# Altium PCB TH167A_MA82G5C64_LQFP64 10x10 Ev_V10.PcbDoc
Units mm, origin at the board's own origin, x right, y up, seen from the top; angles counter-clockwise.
Board outline 72.4 x 66 mm, 2 copper layers (Top Layer, Bottom Layer); 56 components, 82 nets, 364 pads, 164 vias.
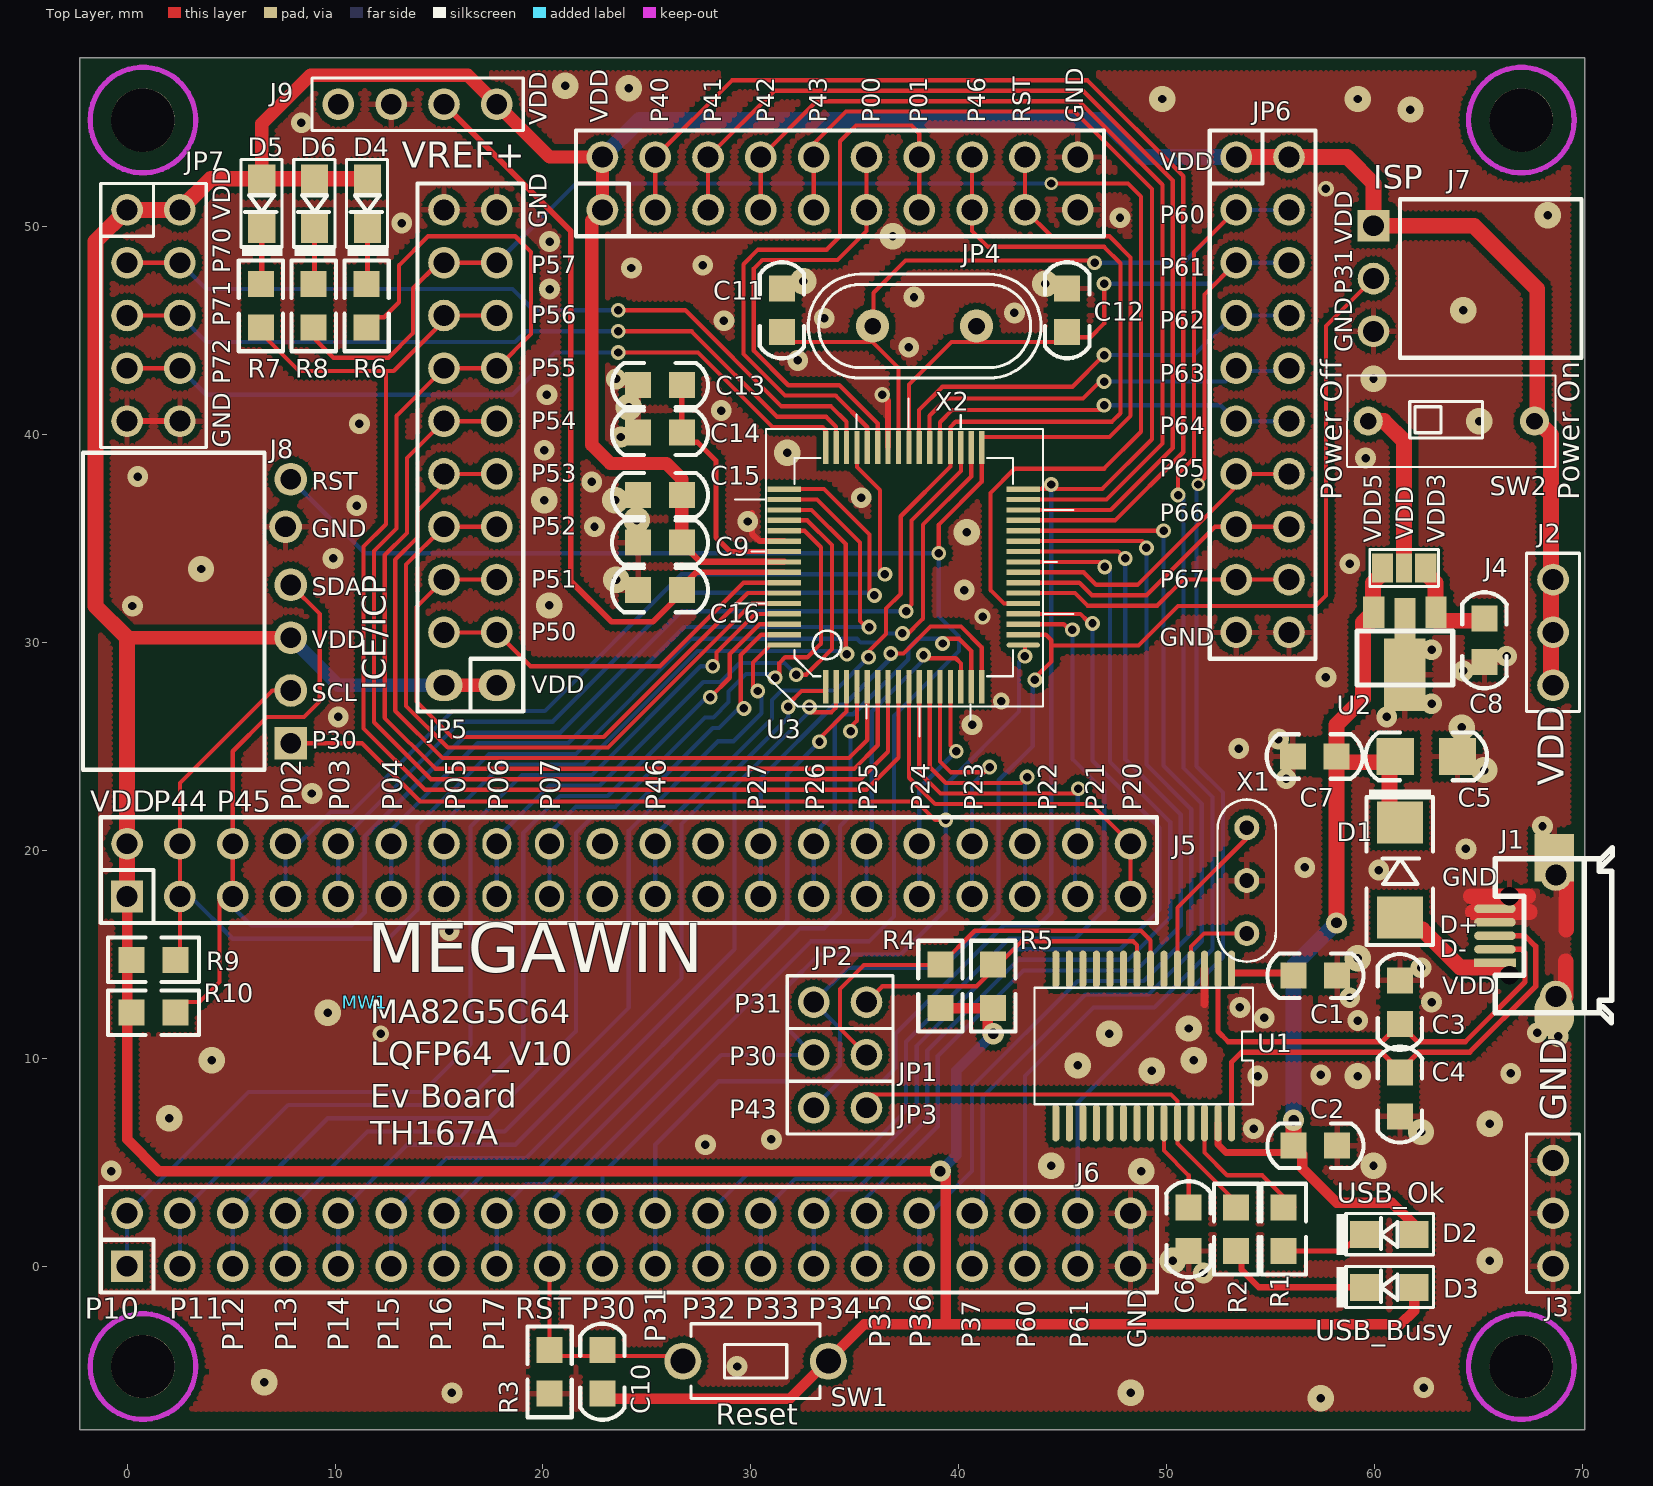
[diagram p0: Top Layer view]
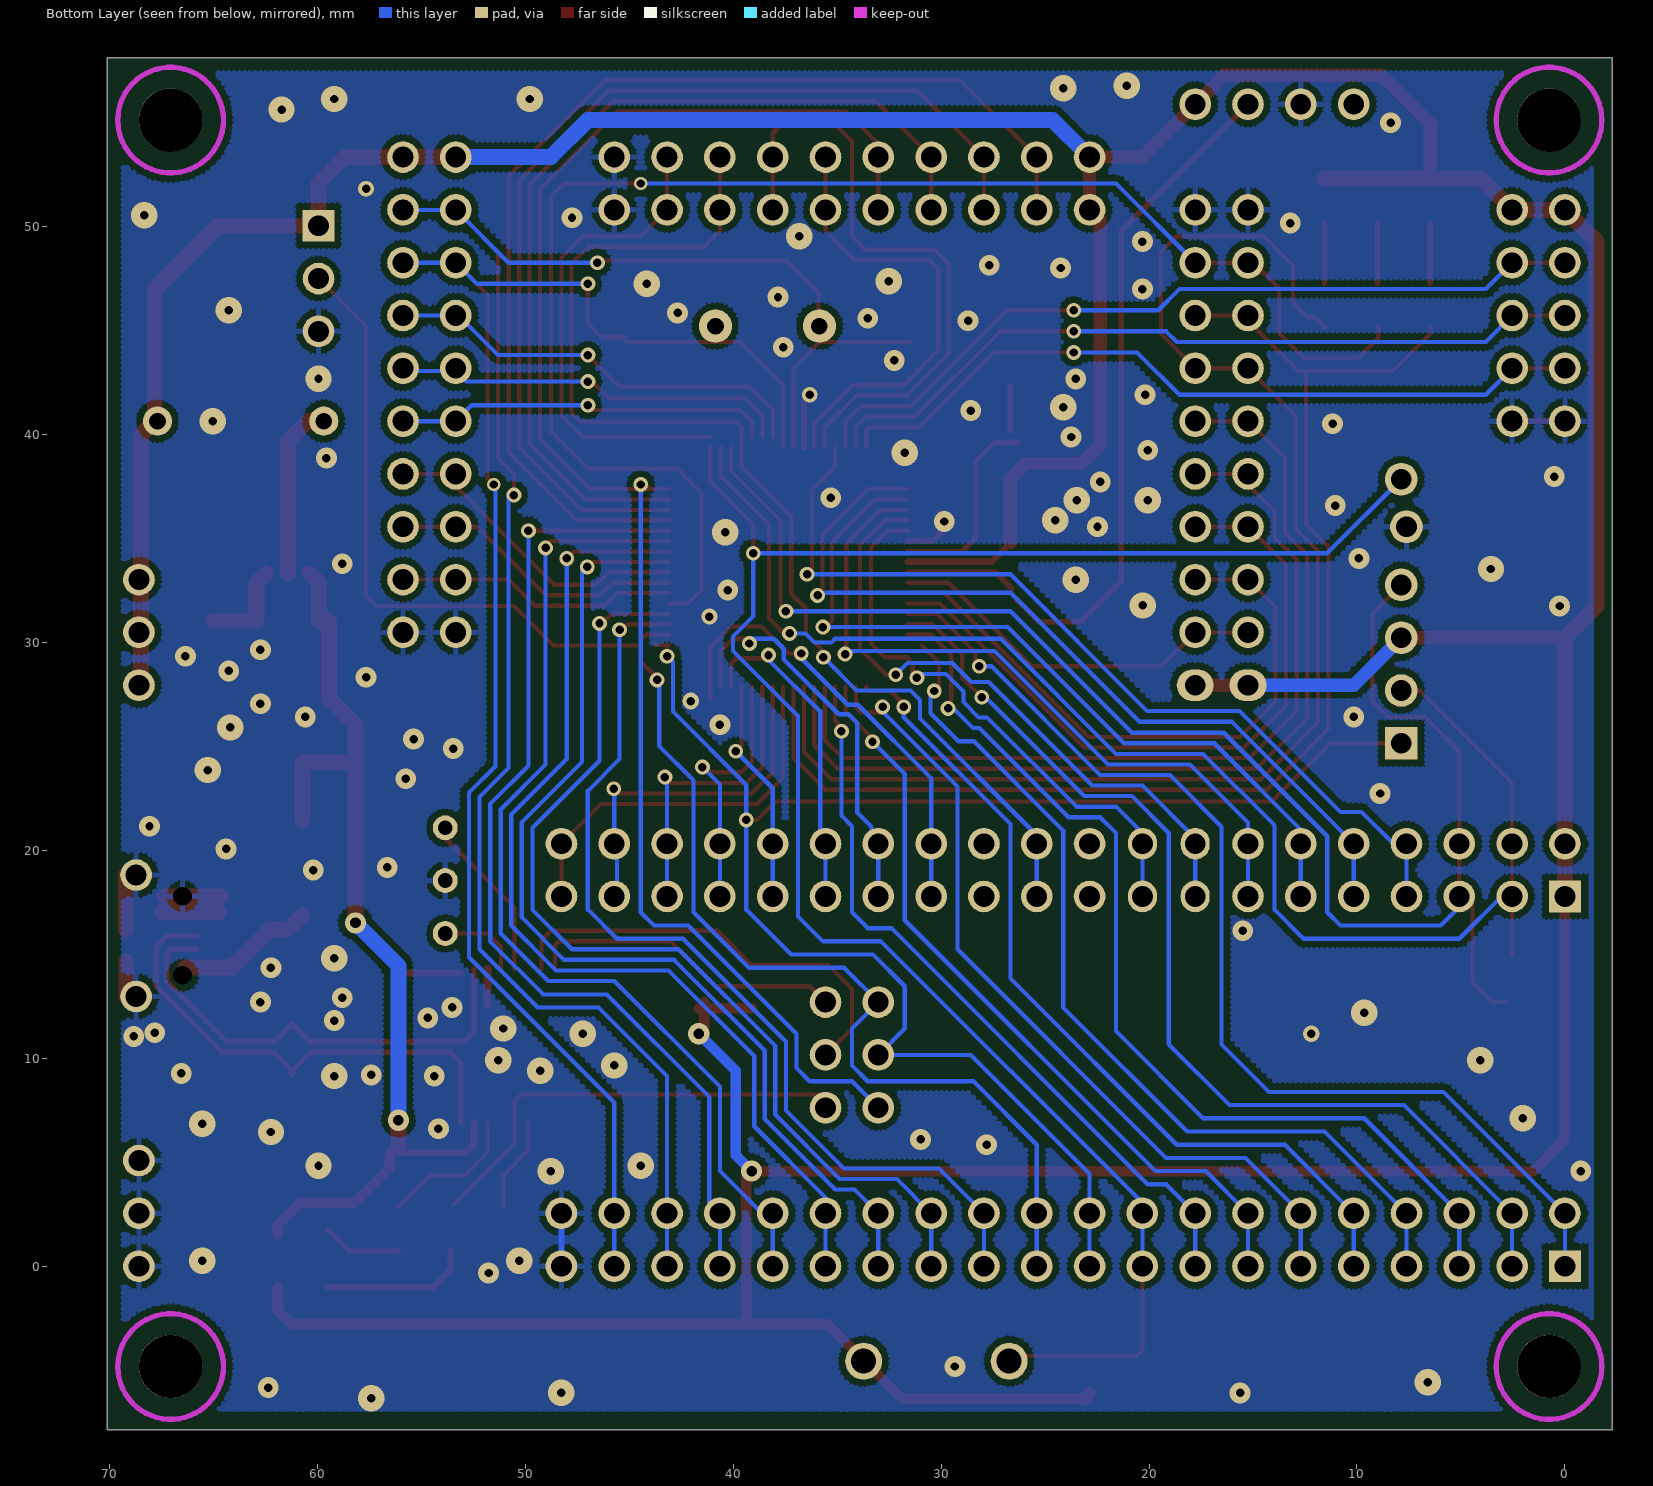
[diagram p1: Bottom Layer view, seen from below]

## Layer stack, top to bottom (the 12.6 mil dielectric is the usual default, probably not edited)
Top Layer: signal copper 0.0356
Dielectric: dielectric 0.32, FR-4, Dk 4.8
Bottom Layer: signal copper 0.0356

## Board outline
-2.286,-7.874 70.114,-7.874 70.114,58.126 -2.286,58.126

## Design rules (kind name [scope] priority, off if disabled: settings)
Clearance 12 [All] p1 off: gap=0.305
Clearance 10 [All] p2 off: gap=0.254
Clearance 6 [All] p3: gap=0.152
ComponentClearance [All] p1 off: gap=0.254 collisioncheckmode=3 verticalgap=0.254 showdistances=FALSE
HoleSize [All] p1: absolutevalues=TRUE maxlimit=12.7 minlimit=0.025 maxpercent=80.000 minpercent=20.000
MinimumSolderMaskSliver [All] p1 off: minsoldermaskwidth=0.254
PolygonConnect VIA [ISVIA] p1: connectstyle=Direct reliefconductorwidth=0.254 reliefentries=4 polygonreliefangle="90 Angle"
PolygonConnect [All] p2: connectstyle=Relief reliefconductorwidth=0.254 reliefentries=4 polygonreliefangle="90 Angle"
RoomDefinition "TH167A_MA82G5C64_LQFP64 10x10 Ev_V10" [InComponentClass('TH167A_MA82G5C64_LQFP64 10x10 Ev_V10')] p1: confinementstyle=ConfineIn formatcopy=TRUE lockcomponents=FALSE outline -14.732,-20.32 80.137,-20.32 80.137,67.056 -14.732,67.056
RoutingVias [All] p1: holewidth=0.406 width=0.635 viastyle="Through Hole" minholewidth=0.406 minwidth=0.61 maxholewidth=0.711 maxwidth=1.27
SilkToSilkClearance [All] p1 off: silktosilkclearance=0.254
SilkscreenOverComponentPads [All] p1 off: minsilkscreentomaskgap=0.254
SolderMaskExpansion [All] p1 off: expansion=0.102
Width [All] p1: maxlimit=5.08 minlimit=0.152 preferedwidth=0.254
23 further rules are at their usual default settings.

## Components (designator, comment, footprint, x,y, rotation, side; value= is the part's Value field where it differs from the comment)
C1 "4.7uF" 0805C 57.15,13.97 r0 top
C2 "0.1uF" 0805C 57.15,5.791 r180 top
C3 "15pF" 0805C 61.214,12.7 r90 top
C4 "15pF" 0805C 61.214,8.255 r270 top
C5 "4.7uF" 1206C 62.484,24.511 r0 top
C6 "0.1uF" 0805C 51.054,1.778 r90 top
C7 "0.1uF" 0805C 57.116,24.511 r180 top
C8 "4.7uF" 0805C 65.278,30.099 r270 top
C9 "0.1uF" 0805C 25.629,34.798 r0 top
C10 "1u" 0805C 22.86,-5.08 r90 top
C11 "NC" 0805C 31.496,45.974 r90 top
C12 "NC" 0805C 45.212,45.974 r90 top
C13 "4.7uF" 0805C 25.629,42.371 r180 top
C14 "0.1uF" 0805C 25.629,40.085 r0 top
C15 "4.7uF" 0805C 25.629,37.084 r180 top
C16 "0.1uF" 0805C 25.629,32.512 r180 top
D1 "1N5817" D5817_SMD_1 61.214,19.05 r270 top
D2 "Yellow" 0805D 60.706,1.524 r180 top
D3 "Red" 0805D 60.706,-1.016 r180 top
D4 "Green" 0805D 11.557,51.103 r270 top
D5 "Red" 0805D 6.477,51.103 r270 top
D6 "Green" 0805D 9.017,51.103 r270 top
J1 "Micro USB母座" JACK_USB_SMD290X220P065 65.786,15.89 r180 top
J2 "*" PS3P254 68.58,27.94 r90 top
J3 "*" PS3P254 68.58,5.08 r270 top
J4 "*" JUMP3_SMD 61.417,33.579 r0 top
J5 "CON40A" PS20X2P254#1 0,17.78 r0 top
J6 "CON40A" PS20X2P254#2 0,0 r0 top
J7 "*" PS3P254f_90 59.944,50.038 r270 top
J8 "*" PS6P254F_90 7.874,25.146 r90 top locked
J9 "CON4" PS4P254 17.78,55.88 r180 top
JP1 "JUMPER2" PS2P254 33.02,10.16 r0 top
JP2 "JUMPER2" PS2P254 33.02,12.7 r0 top
JP3 "JUMPER2" PS2P254 33.02,7.62 r0 top
JP4 "*" PS10X2P254#1 22.86,50.8 r0 top
JP5 "*" PS10X2P254#2 17.78,27.94 r90 top
JP6 "*" PS10X2P254#1 53.34,53.34 r270 top
JP7 "CON5X2" PS5X2P254 0,50.8 r270 top
MW1 "MW-A4" MEGAWIN_T 11.43,12.7 r0 top
R1 "1K" 0805R 55.626,1.778 r270 top
R2 "1K" 0805R 53.34,1.778 r270 top
R3 "47K" 0805R 20.32,-5.08 r90 top
R4 "4.7K" 0805R 39.116,13.462 r90 top
R5 "4.7K" 0805R 41.656,13.462 r90 top
R6 "1K" 0805R 11.516,46.184 r90 top
R7 "1K" 0805R 6.436,46.184 r90 top
R8 "1K" 0805R 8.976,46.184 r90 top
R9 "4.7K" 0805R 1.27,14.732 r180 top
R10 "4.7K" 0805R 1.27,12.192 r180 top
SW1 "SW TACT-SPST" SW_T_2P 30.226,-4.572 r180 top
SW2 "-" DIP2_SW 59.69,40.64 r0 top
U1 "MA101_TSSOP28" SSOP28_220P065 48.891,10.588 r180 top
U2 "AIC1734-33(SOT-89)" SOT89 61.454,31.445 r180 top
U3 "MG82FG5C64" QFP64_10X10P050 33.6,27.87 r90 top locked (schematic designator U1)
X1 "6MHz" X3P 53.848,16.002 r90 top
X2 "NC" X49U 38.354,45.212 r180 top

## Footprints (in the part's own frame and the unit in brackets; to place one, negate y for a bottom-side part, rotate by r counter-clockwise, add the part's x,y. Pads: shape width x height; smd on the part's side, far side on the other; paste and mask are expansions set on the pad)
0805C [mm]
  rect 1.25x1.25 smd: 1(-1.05,0) 2(1.05,0)
  silkscreen extent -2.31,-1.07 2.31,1.07
0805D [mm]
  rect 1.4x1.3 smd: 1(-1.192,0) 2(1.192,0)
  silkscreen extent -2.12,-1 2.53,0.98
0805R [mm]
  rect 1.25x1.25 smd: 1(-1.05,0) 2(1.05,0)
  silkscreen extent -2.18,-1.07 2.18,1.07
1206C [mm]
  rect 1.8x1.8 smd: 1(-1.5,0) 2(1.5,0)
  silkscreen extent -2.92,-1.15 2.92,1.16
D5817_SMD_1 [mil]
  rect 80x86.61 smd: 1(90,0) 2(-90,0)
  silkscreen extent -153,-63 142,63
DIP2_SW [mm]
  round 1.4 hole 0.8: 1(0,0) 2(8,0)
  silkscreen extent -1.02,-2.2 9.02,2.2
JACK_USB_SMD290X220P065 [mm]
  rect 1.9x1.8 on Mech2: 0(-2.85,-1.15) 0(-2.85,1.15)
  round 0.8 hole 0.9 unplated: 1(-0.7,1.9) 5(-0.7,-1.9)
  rect 2x0.4 smd: 1(0,1.3)
  oval 2x0.4 smd: 2(0,0.65) 3(0,0) 4(0,-0.65) 5(0,-1.3)
  round 1.524 hole 1: 5(-2.931,2.921) 5(-2.931,-2.921)
  oval 1.9x2.3 smd: 5(-2.85,3.75)
  rect 1.9x2.3 smd: 5(-2.85,-3.75)
  silkscreen extent -5.65,-4.25 -0.01,4.2
JUMP3_SMD [mil]
  rect 40x55 smd: 1(-41,0) 3(41,0)
  rect 30x55 smd: 2(0,0)
  silkscreen extent -65,-35 65,35
MEGAWIN_T [mm]
PS2P254 [mil]
  round 60 hole 39.37: 1(0,0) 2(100,0)
  silkscreen extent -50,-50 150,50
PS3P254 [mil]
  round 60 hole 39.37: 1(0,0) 2(100,0) 3(200,0)
  silkscreen extent -50,-50 250,50
PS3P254f_90 [mil]
  rect 60x60 hole 39.37: 1(0,0)
  round 60 hole 39.37: 2(100,0) 3(200,0)
  silkscreen extent -50,50 250,394
PS4P254 [mil]
  round 60 hole 39.37: 1(0,0) 2(100,0) 3(200,0) 4(300,0)
  silkscreen extent -50,-50 350,50
PS5X2P254 [mil]
  round 60 hole 39.37: 1(0,0) 2(0,100) 3(100,0) 4(100,100) 5(200,0) 6(200,100) 7(300,0) 8(300,100) 9(400,0) 10(400,100)
  silkscreen extent -50,-50 450,150
PS6P254F_90 [mil]
  rect 62x62 hole 39.37: 1(0,0)
  round 62 hole 39.37: 2(100,0) 3(200,0) 4(300,0) 5(410,10) 6(500,0)
  silkscreen extent -50,50 550,394
PS10X2P254#1 [mil]
  round 60 hole 39.37: 1(0,0) 2(0,100) 3(100,0) 4(100,100) 5(200,0) 6(200,100) 7(300,0) 8(300,100) 9(400,0) 10(400,100) 11(500,0) 12(500,100) 13(600,0) 14(600,100) 15(700,0) 16(700,100) 17(800,0) 18(800,100) 19(900,0) 20(900,100)
  silkscreen extent -50,-50 950,150
PS10X2P254#2 [mil]
  oval 60x70 hole 39.37: 1(0,0) 2(0,100)
  round 60 hole 39.37: 3(100,0) 4(100,100) 5(200,0) 6(200,100) 7(300,0) 8(300,100) 9(400,0) 10(400,100) 11(500,0) 12(500,100) 13(600,0) 14(600,100) 15(700,0) 16(700,100) 17(800,0) 18(800,100) 19(900,0) 20(900,100)
  silkscreen extent -50,-50 950,150
PS20X2P254#1 [mil]
  rect 60x60 hole 39.37: 1(0,0)
  round 60 hole 39.37: 2(0,100) 3(100,0) 4(100,100) 5(200,0) 6(200,100) 7(300,0) 8(300,100) 9(400,0) 10(400,100) 11(500,0) 12(500,100) 13(600,0) 14(600,100) 19(900,0) 20(900,100) 21(1000,0) 22(1000,100) 23(1100,0) 24(1100,100) 25(1200,0) 26(1200,100) 27(1300,0) 28(1300,100) 29(1400,0) 30(1400,100) 31(1500,0) 32(1500,100) 33(1600,0) 34(1600,100) 35(1700,0) 36(1700,100) 37(1800,0) 38(1800,100) 39(1900,0) 40(1900,100)
  oval 55x60 hole 39.37: 15(700,0) 16(700,100) 17(800,0) 18(800,100)
  silkscreen extent -50,-50 1950,150
PS20X2P254#2 [mil]
  rect 60x60 hole 39.37: 1(0,0)
  round 60 hole 39.37: 2(0,100) 3(100,0) 4(100,100) 5(200,0) 6(200,100) 7(300,0) 8(300,100) 9(400,0) 10(400,100) 11(500,0) 12(500,100) 13(600,0) 14(600,100) 15(700,0) 16(700,100) 17(800,0) 18(800,100) 19(900,0) 20(900,100) 21(1000,0) 22(1000,100) 23(1100,0) 24(1100,100) 25(1200,0) 26(1200,100) 27(1300,0) 28(1300,100) 29(1400,0) 30(1400,100) 31(1500,0) 32(1500,100) 33(1600,0) 34(1600,100) 35(1700,0) 36(1700,100) 37(1800,0) 38(1800,100) 39(1900,0) 40(1900,100)
  silkscreen extent -50,-50 1950,150
QFP64_10X10P050 [mm]
  rect 1.6x0.254 smd: 1(0,0) 2(0,-0.5) 3(0,-1) 4(0,-1.5) 5(0,-2) 6(0,-2.5) 7(0,-3) 8(0,-3.5) 9(0,-4) 10(0,-4.5) 11(0,-5) 12(0,-5.5) 13(0,-6) 14(0,-6.5) 15(0,-7) 16(0,-7.5) 33(11.5,-7.5) 34(11.5,-7) 35(11.5,-6.5) 36(11.5,-6) 37(11.5,-5.5) 38(11.5,-5) 39(11.5,-4.5) 40(11.5,-4) 41(11.5,-3.5) 42(11.5,-3) 43(11.5,-2.5) 44(11.5,-2) 45(11.5,-1.5) 46(11.5,-1) 47(11.5,-0.5) 48(11.5,0)
  oval 0.254x1.6 smd: 17(2,-9.5)
  rect 0.254x1.6 smd: 18(2.5,-9.5) 19(3,-9.5) 20(3.5,-9.5) 21(4,-9.5) 22(4.5,-9.5) 23(5,-9.5) 24(5.5,-9.5) 25(6,-9.5) 26(6.5,-9.5) 27(7,-9.5) 28(7.5,-9.5) 29(8,-9.5) 30(8.5,-9.5) 31(9,-9.5) 32(9.5,-9.5) 49(9.5,2) 50(9,2) 51(8.5,2) 52(8,2) 53(7.5,2) 54(7,2) 55(6.5,2) 56(6,2) 57(5.5,2) 58(5,2) 59(4.5,2) 60(4,2) 61(3.5,2) 62(3,2) 63(2.5,2) 64(2,2)
  silkscreen extent -2.4,-11.92 13.86,4.36
SOT89 [mm]
  rect 1.016x1.5 smd: 1(-1.5,0) 3(1.5,0)
  rect 2x3.5 smd: 2(0,3)
  rect 1.016x2.6 smd: 2(0,0.6)
  silkscreen extent -2.3,0.9 2.3,3.5
SSOP28_220P065 [mm]
  oval 0.343x1.778 smd: 1(-4.225,-3.7) 2(-3.575,-3.7) 3(-2.925,-3.7) 4(-2.275,-3.7) 5(-1.625,-3.7) 6(-0.975,-3.7) 7(-0.325,-3.7) 8(0.325,-3.7) 9(0.975,-3.7) 10(1.625,-3.7) 11(2.275,-3.7) 12(2.925,-3.7) 13(3.575,-3.7) 14(4.225,-3.7) 15(4.225,3.7) 16(3.575,3.7) 17(2.925,3.7) 18(2.275,3.7) 19(1.625,3.7) 20(0.975,3.7) 21(0.325,3.7) 22(-0.325,3.7) 23(-0.975,3.7) 24(-1.625,3.7) 25(-2.275,3.7) 26(-2.925,3.7) 27(-3.575,3.7) 28(-4.225,3.7)
  silkscreen extent -5.25,-2.8 5.25,2.8
SW_T_2P [mm]
  round 1.778 hole 1.2: 1(-3.5,0) 2(3.5,0)
  silkscreen extent -3.1,-1.8 3.1,1.8
X3P [mm]
  round 1.2 hole 0.711: 1(0,0) 2(5.08,0) 3(2.54,0)
  silkscreen extent -1.36,-1.4 6.44,1.4
X49U [mm]
  round 1.6 hole 0.8: 1(-2.5,0) 2(2.5,0)
  silkscreen extent -5.6,-2.5 5.6,2.5

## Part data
C1 C5 C8 C13 C15: library part CAP
C2 C3 C4 C6 C7 C9 C14 C16: library part "CAP NP"
C10: library part C
C11 C12: library part "C NP"
D1: library part DIODE_ZD, "Schottky Diode"
D2 D3 D4 D5 D6: library part LED
J1: library part CON5, "Connector"
J2 J3 J4 J7: library part CON3
J8: library part CON6
JP4 JP5 JP6: library part CON10X2
R1 R2 R4 R5 R6 R7 R8: library part R_Dup1
R3 R9 R10: library part R
SW2: library part SW-2
U2: library part AIC1734-33(SOT-89)_0
U3: library part MG82FG5C64_LQFP64
X1: library part CRYSTAL_RC
X2: library part CRYSTAL

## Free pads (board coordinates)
  round 3.048 hole 3.048 unplated: 0(0.762,-4.826) 0(0.762,55.118) 0(67.056,-4.826) 0(67.056,55.118)

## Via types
v1: diameter 1, hole 0.406, Top Layer to Bottom Layer, tented both sides, 66 vias
v2: diameter 0.711, hole 0.406, Top Layer to Bottom Layer, tented both sides, 44 vias
v3: diameter 1.27, hole 0.406, Top Layer to Bottom Layer, tented both sides, 43 vias
v4: diameter 1.016, hole 0.508, Top Layer to Bottom Layer, tented both sides, 4 vias
v5: diameter 0.762, hole 0.406, Top Layer to Bottom Layer, tented both sides, 3 vias
v6: diameter 0.8, hole 0.406, Top Layer to Bottom Layer, tented both sides, 2 vias
v7: diameter 0.635, hole 0.406, Top Layer to Bottom Layer, tented both sides, 2 vias

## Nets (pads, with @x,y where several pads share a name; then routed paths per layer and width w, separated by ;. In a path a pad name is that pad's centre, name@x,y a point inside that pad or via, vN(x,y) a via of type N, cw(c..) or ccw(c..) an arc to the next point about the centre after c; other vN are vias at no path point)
D+: C4.1 J1.3 U1.28 | length 24.2
  Top Layer w0.254: U1.28 53.116,9.809 53.594,10.287 60.325,10.287 61.151,9.461 C4.1@61.151,9.305 ; C4.1@61.214,9.178 61.277,9.242 61.277,9.461 62.103,10.287 64.57,10.287 67.742,13.459 67.742,15.38 67.232,15.89 J1.3
D-: C3.1 J1.2 U1.2 | length 22.8
  Top Layer w0.254: U1.2 52.466,11.288 52.959,10.795 60.359,10.795 C3.1 62.069,10.795 64.36,10.795 67.234,13.669 67.234,15.073 67.067,15.24 J1.2
GND_POWER: C1.2 C2.1 C3.2 C4.2 C5.2 C6.1 C7.2 C8.2 C9.1 C11.2 C12.2 C13.2 C14.1 C15.2 C16.2 J1.4 J1.5 J3.1 J3.2 J3.3 J6.39 J6.40 J7.3 J8.5 J9.3 JP4.19 JP4.20 JP5.19 JP5.20 JP6.19 JP6.20 JP7.9 JP7.10 R3.1 U1.3 U2.2 U3.42 U3.54 X1.3 | length 21.6
  Top Layer w0.279: JP7.9 JP7.10@2.286,40.64 ; v1@30.048,36.22 30.048,35.23 30.408,34.87 U3.54 ; v5(36.322,41.91) 36.6,41.632 U3.42
  Top Layer w0.381: 51.816,12.598 U1.3
  Top Layer w0.762: 64.63,17.79 66.486,17.79 67.368,17.79 ; 64.724,17.04 67.462,17.04 ; J1.5@69.19,12.969 69.19,14.647 ; 69.215,16.182 J1.5@69.215,18.811
  Bottom Layer w0.279: J6.39 J6.40
  other v1: 15.621,-6.096 62.357,-5.842 29.337,-4.826 51.765,-0.329 -0.762,4.572 27.813,5.842 30.988,6.096 54.178,6.604 54.381,9.144 57.404,9.195 66.548,9.271 68.834,11.049 67.818,11.227 59.182,11.811 54.686,11.938 53.518,12.446 62.738,12.7 58.801,12.913 62.23,14.351 15.494,16.129 60.198,19.05 56.642,19.177 64.389,20.066 68.072,21.158 8.89,22.733 55.753,23.444 53.467,24.892 55.372,25.349 40.64,26.035 10.16,26.416 60.579,26.416 62.738,27.051 57.658,28.321 64.262,28.626 66.345,29.337 62.738,29.642 0.254,31.75 40.259,32.512 58.801,33.782 9.906,34.036 22.479,35.56 29.845,35.814 11.049,36.576 35.306,36.957 22.352,37.719 0.508,37.973 59.563,38.862 20.066,39.243 23.749,39.878 11.176,40.513 28.575,41.148 20.193,41.91 23.522,42.672 32.258,43.561 37.592,44.196 28.702,45.466 33.528,45.593 42.672,45.847 37.846,46.609 20.32,46.99 24.257,48.006 27.686,48.133 20.32,49.276 13.208,50.165 47.752,50.419 8.382,54.991
  other v3: 57.404,-6.35 48.26,-6.096 6.604,-5.588 50.292,0.254 65.532,0.254 48.768,4.572 44.45,4.826 59.944,4.826 62.23,6.452 65.532,6.858 2.032,7.112 59.182,9.144 49.276,9.398 45.72,9.652 4.064,9.906 51.308,9.906 47.244,11.176 51.054,11.43 9.652,12.192 59.182,14.808 65.278,23.86 64.186,25.908 20.295,31.775 23.522,33.02 3.556,33.528 40.386,35.306 24.511,35.865 20.066,36.83 23.47,36.83 31.75,39.116 65.024,40.64 24.13,41.304 59.944,42.672 64.262,45.974 44.155,47.244 32.512,47.371 36.83,49.53 68.326,50.546 61.722,55.626 49.784,56.134 59.182,56.134 24.13,56.642 21.082,56.769
  other v5: 41.148,31.242 57.658,51.816
  other v6: 12.192,11.176 42.037,27.178
MA101_RX: JP2.2 R5.2 U1.8 | length 15.6
  Top Layer w0.203: JP2.2 36.322,13.462 40.85,13.462 43.009,15.621 48.387,15.621 48.566,15.442 U1.8 U1.8@48.566,14.403
MA101_TX: JP1.2 R4.2 U1.7 | length 25.3
  Top Layer w0.203: JP1.2 34.29,11.43 34.29,13.335 35.433,14.478 39.116,14.478 40.767,16.129 46.482,16.129 ; 42.545,16.129 46.482,16.129 ; U1.7@49.216,14.291 U1.7 49.216,15.675 48.762,16.129 46.482,16.129
NetC1_1: C1.1 U1.1 | length 2.8
  Top Layer w0.33: U1.1@53.116,14.097 C1.1@55.88,14.097
NetC6_2: C6.2 U1.23 | length 4.6
  Top Layer w0.203: U1.23 49.866,5.557 51.054,4.369 C6.2
NetC13_1: C13.1 C14.2 U3.55 | length 11.8
  Top Layer w0.254: C14.2@26.289,39.624 27.432,39.624 28.321,38.735 28.321,35.052 29.003,34.37 U3.55 ; C14.2@26.679,40.178 C13.1
NetD1_1: D1.1 J1.1 | length 6.7
  Top Layer w0.762: D1.1@60.706,16.891 61.404,16.192 62.293,16.192 64.127,14.359 J1.1@66.35,14.359
NetD2_2: D2.2 R1.2 | length 3.8
  Top Layer w0.254: R1.2@56.134,0.728 58.464,0.728 D2.2@59.514,1.778
NetD3_2: D3.2 R2.2 | length 7.2
  Top Layer w0.305: R2.2@53.594,0.728 53.594,-0.178 54.432,-1.016 D3.2
NetD4_2: D4.2 R6.2 | length 2.9
  Top Layer w0.254: R6.2@11.557,47.275 D4.2 D4.2@11.557,50.165
NetD5_2: D5.2 R7.2 | length 2.9
  Top Layer w0.254: R7.2@6.477,47.275 D5.2 D5.2@6.477,50.165
NetD6_2: D6.2 R8.2 | length 2.9
  Top Layer w0.254: R8.2@9.017,47.275 D6.2 D6.2@9.017,50.165
NetJ4_2: J4.2 SW2.1 | length 8.5
  Top Layer w0.762: SW2.1 60.452,40.64 61.417,39.675 J4.2 J4.2@61.417,33.325
NetU1_4: U1.4 X1.1 | length 4.5
  Top Layer w0.203: U1.4 51.166,15.367 51.801,16.002 X1.1 X1.1@54.356,16.002
NetU1_5: U1.5 X1.2 | length 8.4
  Top Layer w0.203: U1.5 50.516,17.242 X1.2@54.356,21.082
P00: JP4.11 JP4.12 U3.43 | length 22.2
  Top Layer w0.203: JP4.12 JP4.11 35.56,49.784 34.163,48.387 30.552,48.387 30.142,47.977 30.142,44.026 31.801,42.367 34.254,42.367 36.1,40.521 U3.43
P01: JP4.13 JP4.14 U3.44 | length 30.5
  Top Layer w0.203: U3.44 35.6,40.346 34.079,41.867 31.64,41.867 29.642,43.866 29.642,48.184 30.345,48.887 33.647,48.887 34.29,49.53 34.29,54.102 35.052,54.864 37.719,54.864 38.1,54.483 JP4.14 JP4.13
P02: J5.7 J5.8 U3.45 | length 43.3
  Top Layer w0.203: U3.45 35.1,38.433 36.212,37.321 v2@36.212,33.274
  Bottom Layer w0.203: J5.7 J5.8 8.255,20.32 9.779,21.844 10.795,21.844 15.646,26.695 20.091,26.695 26.67,33.274 v2(36.449,33.274)
P03: J5.9 J5.10 U3.49 | length 40.9
  Top Layer w0.203: U3.49 33.521,37.37 35.704,35.187 v2@35.704,32.258
  Bottom Layer w0.203: J5.9 J5.10 16.027,26.187 20.472,26.187 26.67,32.385 35.56,32.385
  other v2: 35.941,32.258
P04: J5.11 J5.12 U3.50 | length 39
  Top Layer w0.203: U3.50 33.183,36.87 35.247,34.806 35.247,31.021 v2@35.611,30.658
  Bottom Layer w0.203: J5.11 J5.12 12.7,20.98 16.866,25.146 21.209,25.146 26.797,30.734 35.535,30.734 v2@35.611,30.658
  other v2: 35.687,30.734
P05: J5.13 J5.14 U3.51 | length 35.5
  Top Layer w0.203: U3.51 32.921,36.37 34.561,34.73 34.561,29.523 v2@34.696,29.388
  Bottom Layer w0.203: J5.13 J5.14 15.24,21.336 18.034,24.13 21.971,24.13 27.432,29.591 34.468,29.591 v2(34.62,29.439) ; v2@34.501,29.32 v2@34.561,29.259
P06: J5.15 J5.16 U3.52 | length 30.9
  Top Layer w0.203: U3.52 32.71,35.87 33.901,34.679 33.901,29.685 32.664,28.448 v2(32.182,28.448)
  Bottom Layer w0.203: J5.15 J5.16 17.78,20.574 20.32,23.114 22.733,23.114 27.711,28.092 28.55,28.092 29.464,29.007 31.623,29.007 v2(32.182,28.448)
P07: J5.17 J5.18 U3.53 | length 27.2
  Top Layer w0.203: v2@31.369,28.27 31.369,29.007 31.648,29.286 32.715,29.286 33.368,29.939 33.368,34.577 32.575,35.37 U3.53
  Bottom Layer w0.203: J5.17 J5.18 20.32,20.828 21.59,22.098 23.495,22.098 27.788,26.391 28.194,26.391 28.931,27.127 28.931,27.635 29.769,28.473 30.912,28.473 v2@31.115,28.27
  other v2: 31.166,28.296
P10: J6.1 J6.2 U3.61 | length 52.4
  Top Layer w0.203: v2@28.346,28.854 28.346,29.515 30.202,31.37 U3.61
  Bottom Layer w0.203: J6.1 J6.2 5.842,8.382 14.224,8.382 16.51,10.668 16.51,21.133 18.999,23.622 22.352,23.622 27.584,28.854 v2(28.169,28.854)
P11: J6.3 J6.4 U3.62 | length 51.2
  Top Layer w0.203: v2(28.042,27.356) 28.981,28.296 28.981,29.439 30.413,30.87 U3.62
  Bottom Layer w0.203: J6.3 J6.4 7.747,7.747 16.129,7.747 19.05,10.668 19.05,17.526 ; 19.05,16.256 19.05,17.526 ; v2@27.953,27.445 23.114,22.606 20.828,22.606 19.05,20.828 19.05,17.526
P12: J6.5 J6.6 U3.63 | length 48.1
  Top Layer w0.203: v2@29.515,26.822 29.515,29.388 30.497,30.37 U3.63
  Bottom Layer w0.203: J6.5 J6.6 9.652,7.112 17.399,7.112 21.59,11.303 21.59,15.748 ; 21.59,15.494 21.59,15.748 ; v2(29.667,26.822) 29.413,26.822 28.473,25.883 28.169,25.883 23.876,21.59 22.352,21.59 21.59,20.828 21.59,15.748
P13: J6.7 J6.8 U3.64 | length 44.8
  Top Layer w0.203: v2@30.277,27.559 30.099,27.737 30.099,29.032 U3.64@30.912,29.845
  Bottom Layer w0.203: J6.7 J6.8 11.557,6.477 18.161,6.477 24.13,12.446 24.13,16.129 ; 24.13,15.494 24.13,16.129 ; v2(30.328,27.661) 30.505,27.483 30.505,26.594 29.159,25.248 28.423,25.248 24.13,20.955 24.13,16.129
P14: J6.9 J6.10 U3.1 | length 41.6
  Top Layer w0.203: v2@31.801,27.026 32.436,27.661 33.6,27.661 U3.1
  Bottom Layer w0.203: J6.9 J6.10 13.462,5.842 18.669,5.842 26.67,13.843 26.67,16.51 ; 26.67,16.256 26.67,16.51 ; v2@31.801,27.026 v2(31.801,26.899) 31.801,26.391 26.67,21.26 26.67,16.51
P15: J6.11 J6.12 U3.2 | length 39.6
  Top Layer w0.203: v2@32.817,26.645 33.884,26.645 34.1,26.861 U3.2
  Bottom Layer w0.203: J6.11 J6.12 15.367,5.207 19.177,5.207 29.21,15.24 29.21,23.063 v2@32.804,26.657
  other v2: 32.817,26.899
P16: J6.13 J6.14 U3.3 | length 37.3
  Top Layer w0.203: v2@33.223,25.298 34.6,26.675 U3.3
  Bottom Layer w0.203: J6.13 J6.14 17.272,4.572 19.685,4.572 31.75,16.637 31.75,23.673 v2(33.299,25.222)
P17: J6.15 J6.16 U3.4 | length 36.2
  Top Layer w0.203: v2@34.696,25.832 35.1,26.235 U3.4
  Bottom Layer w0.203: J6.15 J6.16 19.177,3.937 20.066,3.937 32.385,16.256 33.528,16.256 34.29,17.018 34.29,21.158 34.798,21.666 v2(34.798,25.73)
P20: J5.39 J5.40 U3.9 | length 18.9
  Top Layer w0.203: U3.9 37.6,23.487 38.862,22.225 46.355,22.225 J5.40 J5.39
P21: J5.37 J5.38 U3.10 | length 17.2
  Top Layer w0.203: U3.10 38.1,23.749 39.116,22.733 v2@45.745,22.733
  Bottom Layer w0.203: J5.38@45.593,20.32 45.593,17.907 J5.37 ; J5.38@45.72,20.701 v2@45.72,23.089
  other v2: 45.745,22.962
P22: J5.35 J5.36 U3.11 | length 14.9
  Top Layer w0.203: U3.11 38.6,24.011 39.37,23.241 43.002,23.241 v2(43.282,23.52)
  Bottom Layer w0.203: J5.35 J5.36 v2@43.18,23.419 ; v2@43.18,23.52 v2@43.18,23.419 ; v2(43.282,23.52) v2@43.18,23.419
P23: J5.33 J5.34 U3.12 | length 12.9
  Top Layer w0.203: U3.12 39.1,24.273 39.624,23.749 41.224,23.749 v2(41.478,24.003)
  Bottom Layer w0.203: J5.33 J5.34 40.64,23.165 v2(41.478,24.003)
P24: J5.31 J5.32 U3.13 | length 11.1
  Top Layer w0.203: U3.13 39.6,25.043 v2(39.878,24.765)
  Bottom Layer w0.203: J5.31 J5.32 38.1,22.987 v2(39.878,24.765) ; v2@39.751,24.892 v2@39.878,25.019
P25: J5.29 J5.30 U3.14 | length 15.6
  Top Layer w0.203: v2(38.303,29.388) 38.456,29.235 39.853,29.235 40.1,28.988 U3.14
  Bottom Layer w0.203: J5.29 J5.30 35.814,20.574 35.814,26.67 38.303,29.159 v2@38.303,29.185
P26: J5.27 J5.28 U3.15 | length 18.8
  Top Layer w0.203: v2@39.218,30.175 40.005,30.175 40.6,29.58 U3.15
  Bottom Layer w0.203: J5.27 J5.28 ; J5.28@33.35,20.65 33.35,21.133 34.036,21.819 34.036,26.123 34.456,26.543 34.925,26.543 37.567,29.185 37.567,29.693 38.049,30.175 v2@39.218,30.175
  other v2: 39.218,29.947
P27: J5.25 J5.26 U3.16 | length 22.4
  Top Layer w0.203: v2(36.728,29.464) 37.338,29.464 38.633,30.759 40.107,30.759 41.1,29.766 U3.16@41.1,27.276
  Bottom Layer w0.203: J5.25 J5.26 30.48,23.47 34.011,27 34.493,27 36.728,29.235 v2(36.728,29.464)
P30/RXD: J6.19 J6.20 J8.1 JP1.1 U3.17 | length 78.7
  Top Layer w0.203: J8.1 J8.1@8.382,25.146 ; J8.1@7.874,25.654 J8.1@8.382,25.146 ; v2(39.37,21.463) 38.862,21.463 37.973,22.352 14.097,22.352 11.303,25.146 J8.1@8.382,25.146 ; U3.17 U3.17@43.18,29.87 ; v2(43.18,29.337) U3.17@43.18,29.87 ; U3.17@43.79,29.87 U3.17@43.18,29.87
  Bottom Layer w0.203: J6.19 J6.20 22.86,4.445 28.575,10.16 JP1.1 31.75,11.43 31.75,13.462 33.274,14.986 37.211,14.986 39.37,17.145 v2(39.37,21.463) 39.37,23.139 42.901,26.67 42.901,29.058 v2(43.18,29.337)
P31/TXD: J6.21 J6.22 J7.2 JP2.1 U3.18 | length 76.4
  Top Layer w0.203: U3.18 44.179,30.37 44.45,30.099 44.45,29.845 ; v2@43.688,28.321 44.45,29.083 44.45,29.845 ; J7.2 57.658,45.212 57.658,32.258 57.15,31.75 50.546,31.75 48.641,29.845 44.45,29.845
  Bottom Layer w0.203: J6.21 J6.22 25.4,5.842 28.448,8.89 33.528,8.89 34.29,9.652 34.29,11.43 JP2.1 34.671,14.351 39.243,14.351 41.91,17.018 41.91,23.368 43.561,25.019 v2@43.561,28.194
  other v2: 43.663,28.194
P32: J6.23 J6.24 U3.19 | length 46.1
  Top Layer w0.203: U3.19 45.051,30.87 v2@45.39,30.531
  Bottom Layer w0.203: J6.23 J6.24 30.099,4.699 34.671,4.699 37.465,7.493 37.465,10.795 42.418,15.748 45.593,15.748 46.99,17.145 46.99,22.86 45.466,24.384 v2(45.466,30.607)
P33: J6.25 J6.26 U3.20 | length 48
  Top Layer w0.203: U3.20 45.846,31.37 v2@46.177,31.039
  Bottom Layer w0.203: J6.25 J6.26 32.131,4.191 34.881,4.191 37.973,7.283 37.973,10.585 42.628,15.24 47.759,15.24 49.657,17.138 49.657,21.082 46.431,24.308 v2(46.431,30.912)
P34: J6.27 J6.28 U3.25 | length 49.8
  Top Layer w0.203: U3.25 46.775,33.87 v2(47.019,33.626)
  Bottom Layer w0.203: J6.27 J6.28 34.163,3.683 35.092,3.683 38.481,7.072 38.481,10.374 42.839,14.732 48.133,14.732 50.165,16.764 50.165,21.361 47.273,24.254 47.273,33.626 v2(47.019,33.626)
P35: J6.29 J6.30 U3.26 | length 49.6
  Top Layer w0.203: U3.26 47.672,34.37 v2(48.006,34.036)
  Bottom Layer w0.203: J6.29 J6.30 35.56,3.302 38.989,6.731 38.989,10.109 43.104,14.224 48.514,14.224 50.673,16.383 50.673,21.717 48.006,24.384 v2(48.006,34.036)
P36: J6.31 J6.32 U3.27 | length 48.4
  Top Layer w0.203: U3.27 48.823,34.87
  Bottom Layer w0.203: J6.31 38.1,2.032 40.64,4.572 40.64,8.636 45.72,13.716 48.895,13.716 51.181,16.002 51.181,21.971 49.022,24.13 v2(49.022,34.544)
P37: J6.33 J6.34 U3.28 | length 49.2
  Top Layer w0.203: U3.28 v2(49.847,35.37)
  Bottom Layer w0.203: J6.33 J6.34 41.148,3.048 41.148,8.128 46.082,13.062 49.13,13.062 51.689,15.621 51.689,22.225 49.847,24.067 v2(49.847,35.37)
P40: JP4.3 JP4.4 U3.29 | length 53.7
  Top Layer w0.203: JP4.3 JP4.4 29.09,57.03 46.184,57.03 50.792,52.421 50.792,39.146 47.516,35.87 U3.29
P41: JP4.5 JP4.6 U3.30 | length 49.3
  Top Layer w0.203: JP4.5 JP4.6 31.13,56.53 45.976,56.53 50.292,52.214 50.292,39.353 47.309,36.37 U3.30
P42: JP4.7 JP4.8 U3.31 | length 44.9
  Top Layer w0.203: JP4.7 JP4.8 33.17,56.03 45.769,56.03 49.792,52.007 49.792,39.56 47.102,36.87 U3.31
P43: JP3.1 JP4.9 JP4.10 U3.32 | length 78
  Top Layer w0.203: JP4.9 JP4.10 33.02,53.975 34.575,55.53 45.562,55.53 49.292,51.8 49.292,39.767 46.895,37.37 43.974,37.37 ; U3.32 43.974,37.37 ; v2@44.323,37.719 43.974,37.37
  Bottom Layer w0.203: JP3.1 34.29,8.89 36.322,8.89 36.957,9.525 36.957,11.176 42.164,16.383 43.815,16.383 44.45,17.018 v2@44.45,37.37
  other v2: 44.45,37.592
P44: J5.3 J5.4 J8.2 R9.1 U3.34 | length 70.4
  Top Layer w0.203: R9.1@2.54,14.952 J5.3 J5.4 2.54,23.241 6.985,27.686 J8.2 ; v2@37.427,30.29 38.278,31.14 38.278,35.662 40.6,37.984 U3.34
  Bottom Layer w0.203: J5.3 3.048,17.78 5.08,15.748 12.573,15.748 13.97,17.145 13.97,21.209 17.399,24.638 21.59,24.638 27.127,30.175 35.103,30.175 35.281,29.997 36.093,29.997 36.525,30.429 v2(37.287,30.429) ; J5.4 J5.4@2.54,20.701
P45: J5.5 J5.6 J8.4 R10.1 U3.35 | length 75.7
  Top Layer w0.203: R10.1@2.847,12.702 3.482,12.702 4.445,13.665 J5.5@4.445,17.78 ; J5.5 J5.6 5.08,24.765 6.731,26.416 8.509,26.416 9.271,27.178 9.271,31.369 J8.4 ; v2@37.389,31.496 37.719,31.826 37.719,35.865 40.1,38.246 U3.35
  Bottom Layer w0.203: J5.5 5.08,17.272 5.969,16.383 10.795,16.383 11.43,17.018 11.43,20.676 16.408,25.654 20.828,25.654 26.67,31.496 v2(37.465,31.496) ; J5.6 J5.6@5.08,20.955
P46: J5.21 J5.22 JP4.15 JP4.16 U3.36 | length 56.7
  Top Layer w0.203: v2@35.662,29.566 36.5,30.404 36.5,31.623 37.211,32.334 37.211,36.068 39.6,38.457 U3.36 39.6,40.362 39.853,40.615 47.371,40.615 47.776,41.02 47.776,48.236 46.99,49.022 41.402,49.022 40.64,49.784 JP4.15 JP4.16
  Bottom Layer w0.203: J5.21 J5.22 25.4,20.726 31.013,26.34 31.013,27.229 31.471,27.686 34.061,27.686 v2(35.662,29.286)
P50: JP5.3 JP5.4 U3.58 | length 18.7
  Top Layer w0.203: JP5.4 JP5.3 19.406,28.854 25.628,28.854 29.643,32.87 U3.58
P51: JP5.5 JP5.6 U3.59 | length 30.2
  Top Layer w0.203: JP5.5 JP5.6 13.919,31.699 13.919,27.153 15.629,25.443 22.923,25.443 29.85,32.37 U3.59
P52: JP5.7 JP5.8 U3.60 | length 33.8
  Top Layer w0.203: JP5.7 JP5.8 13.419,33.739 13.419,26.945 15.422,24.943 23.13,24.943 30.058,31.87 U3.60
P53: JP5.9 JP5.10 U3.5 | length 41.5
  Top Layer w0.203: JP5.9 JP5.10 15.24,37.592 13.97,36.322 13.97,35.052 12.895,33.977 12.895,26.707 15.168,24.435 34.722,24.435 35.6,25.313 U3.5
P54: JP5.11 JP5.12 U3.6 | length 46
  Top Layer w0.203: JP5.11 JP5.12 13.462,38.862 13.462,35.262 12.387,34.188 12.387,26.37 14.83,23.927 34.976,23.927 36.1,25.051 U3.6
P55: JP5.13 JP5.14 R6.1 U3.7 | length 68.5
  Top Layer w0.203: R6.1 12.02,45.638 12.364,45.638 13.081,46.355 13.081,48.133 14.478,49.53 18.669,49.53 19.431,48.768 19.431,44.831 JP5.13 ; JP5.13@18.415,43.18 JP5.13 ; U3.7 36.6,24.738 35.281,23.419 14.62,23.419 11.879,26.16 11.879,34.398 12.954,35.473 12.954,40.894 JP5.14 JP5.13
P56: JP5.15 JP5.16 R7.1 U3.8 | length 62.2
  Top Layer w0.203: R7.1 6.436,44.88 8.263,43.053 12.446,43.053 ; JP5.16 15.24,45.466 12.827,43.053 12.446,43.053 ; JP5.16@15.367,45.593 15.494,45.72 JP5.15 ; U3.8 37.1,24.451 35.56,22.911 14.322,22.911 11.371,25.861 11.371,34.608 12.446,35.683 12.446,43.053
P57: JP5.17 JP5.18 R8.1 U3.21 | length 76.5
  Top Layer w0.203: R8.1 8.976,44.634 9.922,43.688 12.573,43.688 13.757,44.872 13.757,47.031 14.986,48.26 JP5.18 JP5.17 ; 41.529,37.084 41.529,32.512 ; U3.21 42.171,31.87 41.529,32.512 ; v7(44.45,52.07) 48.133,52.07 48.768,51.435 48.768,40.132 46.99,38.354 42.693,38.354 41.529,37.19 41.529,32.512
  Bottom Layer w0.203: JP5.17 21.59,52.07 v7(44.45,52.07)
P60: C11.1 J6.35 J6.36 JP6.3 JP6.4 U3.41 X2.2 | length 91.8
  Top Layer w0.203: C11.1@31.496,44.416 31.53,44.45 X2.2@35.854,44.45 ; X2.2@35.854,44.958 X2.2@35.854,44.45 ; X2.2@35.894,44.958 35.894,46.816 37.44,48.362 v2@46.38,48.362 ; U3.41 37.1,43.204 X2.2@35.854,44.45 ; v2(50.546,37.084) 50.546,38.1 51.308,38.862 51.308,48.768 JP6.3
  Bottom Layer w0.203: J6.35 J6.36 43.18,9.144 46.482,12.446 49.403,12.446 52.197,15.24 52.197,22.563 50.8,23.96 v2@50.8,37.084 ; v2(46.533,48.26) 50.8,48.26 JP6.3 JP6.4
P61: C12.1 J6.37 J6.38 JP6.5 JP6.6 U3.40 X2.1 | length 77.2
  Top Layer w0.203: U3.40 37.6,42.401 39.649,44.45 C12.1@45.178,44.45 ; C12.1@45.212,44.67 46.321,44.67 46.99,45.339 v2(46.99,47.244) ; v7(51.511,37.592) 51.816,37.897 51.816,46.736 JP6.5
  Bottom Layer w0.203: J6.37 J6.38 45.72,7.874 52.705,14.859 52.705,22.774 51.435,24.044 v7@51.435,37.592 ; v2(46.99,47.244) 52.324,47.244 JP6.5 JP6.6
P62: JP6.7 JP6.8 U3.39 | length 20.9
  Top Layer w0.203: U3.39@38.091,39.903 38.091,41.173 39.208,42.291 45.466,42.291 v2(46.99,43.815)
  Bottom Layer w0.203: v2(46.99,43.815) 51.308,43.815 53.213,45.72 JP6.7 JP6.8
P63: JP6.9 JP6.10 U3.38 | length 19.1
  Top Layer w0.203: U3.38@38.591,39.903 38.591,40.902 39.421,41.732 45.974,41.732 46.787,42.545 v2(46.99,42.545)
  Bottom Layer w0.203: v2(46.99,42.545) 52.832,42.545 53.34,43.053 JP6.10@55.753,43.053
P64: JP6.11 JP6.12 U3.37 | length 18.1
  Top Layer w0.203: U3.37@39.091,39.903 39.091,40.589 39.675,41.173 46.761,41.173 v2(46.99,41.402)
  Bottom Layer w0.203: v2(46.99,41.402) 52.578,41.402 JP6.11 JP6.12
P65: JP6.13 JP6.14 U3.24 | length 15.4
  Top Layer w0.203: U3.24 46.005,33.37 46.609,32.766 48.59,32.766 53.467,37.643 53.467,37.973 53.594,38.1 JP6.14
P66: JP6.15 JP6.16 U3.23 | length 14.4
  Top Layer w0.203: U3.23 45.798,32.87 46.402,32.266 49.03,32.266 52.324,35.56 JP6.15 JP6.16
P67: JP6.17 JP6.18 U3.22 | length 13.8
  Top Layer w0.203: U3.22 45.591,32.37 46.195,31.766 49.546,31.766 50.8,33.02 JP6.17 ; JP6.17@53.594,33.02 JP6.17 ; JP6.18 JP6.17
P70: JP7.3 JP7.4 U3.46 | length 39
  Top Layer w0.203: JP7.3 JP7.4 ; v2(23.622,45.974) 26.848,45.974 31.471,41.351 33.858,41.351 34.6,40.609 U3.46
  Bottom Layer w0.203: JP7.4 3.81,46.99 18.542,46.99 19.558,45.974 v2(23.622,45.974)
P71: JP7.5 JP7.6 U3.47 | length 37.7
  Top Layer w0.203: JP7.5 JP7.6 ; v2(23.622,44.958) 27.153,44.958 31.259,40.851 33.622,40.851 34.1,40.373 U3.47
  Bottom Layer w0.203: JP7.6 3.81,44.45 18.669,44.45 19.177,44.958 v2(23.622,44.958)
P72: JP7.7 JP7.8 U3.48 | length 37.3
  Top Layer w0.203: JP7.7 JP7.8 ; v2(23.622,43.942) 27.457,43.942 31.048,40.351 33.452,40.351 33.6,40.203 U3.48
  Bottom Layer w0.203: JP7.8 3.81,41.91 18.542,41.91 20.574,43.942 v2(23.622,43.942)
RST: C10.2 J6.17 J6.18 J8.6 JP4.17 JP4.18 R3.2 SW1.2 U3.33 | length 116.3
  Top Layer w0.203: J6.17 R3.2 20.608,-4.318 SW1.2@26.543,-4.318 ; v2@39.04,34.061 v2(39.04,34.29) 39.04,35.662 41.1,37.722 U3.33 ; U3.33@41.148,39.878 47.244,39.878 48.26,40.894 48.26,48.514 47.244,49.53 44.45,49.53 JP4.17 JP4.18
  Bottom Layer w0.203: J8.6 11.43,34.29 v2@38.811,34.29 ; J6.17 20.32,2.413 J6.18@20.383,2.476 ; J6.18@20.32,3.175 20.447,3.175 32.893,15.621 35.687,15.621 36.881,16.815 36.881,26.467 40.005,29.591 40.005,30.277 39.04,31.242 v2@39.04,34.061
USB_BUSY: JP3.2 R2.1 U1.24 | length 21.4
  Top Layer w0.203: JP3.2@35.433,8.255 50.206,8.255 50.516,7.945 U1.24 50.516,5.897 R2.1@53.467,2.946
USB_OK: R1.1 U1.26 | length 6.8
  Top Layer w0.203: U1.26 51.816,5.461 52.908,4.369 54.593,4.369 R1.1@56.134,2.828
VDD: C9.2 C10.1 C15.1 D3.1 D4.1 D5.1 D6.1 J2.1 J2.2 J2.3 J5.1 J5.2 J7.1 J8.3 J9.1 JP4.1 JP4.2 JP5.1 JP5.2 JP6.1 JP6.2 JP7.1 JP7.2 R4.1 R5.1 R9.2 R10.2 SW1.1 SW2.2 U3.56 | length 295.7
  Top Layer w0.305: C9.2 26.679,34.764 27.573,33.87 U3.56
  Top Layer w0.508: J5.1 0,6.096 1.524,4.572 v4(39.116,4.572) ; C10.1@23.102,-6.372 31.87,-6.372 35.448,-2.794 39.37,-2.794 ; R4.1 R5.1@41.402,12.412 ; v4@39.37,4.318 39.37,-2.794 ; v4@41.402,11.176 R5.1@41.402,12.412 ; R5.1@41.402,12.7 R5.1@41.402,12.412 ; R5.1 R5.1@41.402,12.412 ; D3.1 61.898,-2.136 61.239,-2.794 39.37,-2.794
  Top Layer w0.635: 0,30.226 J8.3 ; D5.1 6.477,54.94 8.814,57.277 16.383,57.277 J9.1 20.32,53.34 JP4.2 JP4.1 22.352,50.292 22.352,39.497 23.241,38.608 25.933,38.608 26.679,37.863 C15.1 C9.2 ; JP5.2 JP5.1 ; C10.1 C10.1@23.102,-6.372
  Top Layer w0.762: J5.1 J5.2@0,19.941 ; J5.2 0,30.226 -1.524,31.75 -1.524,49.276 JP7.1 JP7.2 4.035,52.295 D5.1 D6.1 D4.1 ; JP6.1 JP6.2 58.674,53.34 59.944,52.07 J7.1 64.77,50.038 67.818,46.99 67.818,40.64 68.478,39.98 J2.1@68.478,27.94
  Bottom Layer w0.508: v4(39.116,4.572) 39.878,5.334 39.878,9.398 v4(41.656,11.176)
  Bottom Layer w0.635: J8.3 10.16,27.94 JP5.2
  Bottom Layer w0.762: JP4.2 24.638,55.118 46.99,55.118 48.768,53.34 JP6.1
VDD3: C8.1 J4.3 U2.1 | length 4.6
  Top Layer w0.762: J4.3@62.459,33.325 62.919,32.865 62.919,31.039 C8.1@65.033,31.039
VDD5: C2.2 C5.1 C7.1 D1.2 D2.1 J4.1 U1.27 U2.3 | length 47.7
  Top Layer w0.33: U1.27 52.466,5.852 52.857,5.461 C2.2@56.041,5.461
  Top Layer w0.5: C2.2 56.515,5.376 56.515,4.699 58.166,3.048 60.833,3.048 61.898,1.983 D2.1
  Top Layer w0.762: C2.2 v4(56.1,7.019) ; v4(58.166,16.51) C7.1 58.166,26.035 59.436,27.305 59.436,30.963 U2.3@59.919,31.445 ; C7.1@58.444,24.233 60.706,24.233 D1.2@60.706,21.463 ; U2.3@59.919,31.039 U2.3@59.919,31.445 ; J4.1@60.376,33.325 59.919,32.868 U2.3@59.919,31.445
  Bottom Layer w0.762: v4(56.1,7.019) 56.1,14.444 v4(58.166,16.51)
VREF+: C16.1 J9.2 U3.57 | length 37.1
  Top Layer w0.279: J9.2 21.336,49.784 21.336,32.944 23.292,30.988 25.298,30.988 C16.1@26.355,32.044 ; C16.1@26.598,32.593 27.376,33.37 U3.57
pads on no net: J1.0 J5.19 J5.20 J5.23 J5.24 J9.4 U1.6 U1.9 U1.10 U1.11 U1.12 U1.13 U1.14 U1.15 U1.16 U1.17 U1.18 U1.19 U1.20 U1.21 U1.22 U1.25

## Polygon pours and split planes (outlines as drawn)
GND_POWER on Bottom Layer "Bottom Layer-No Net" (hatched 90Degree grid 0.254 track 0.254, remove dead copper, pour order 1001): -1.27,-6.883 69.342,-6.883 69.342,57.404 -1.27,57.404
GND_POWER on Top Layer "Bottom Layer-No Net" (hatched 90Degree grid 0.254 track 0.254, remove dead copper, pour order 1001): -1.27,-6.883 69.342,-6.883 69.342,57.404 -1.27,57.404

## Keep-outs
Keep-Out Layer:
  circle w0.254: c67.056,55.118 r2.54
  circle w0.254: c0.762,55.118 r2.54
  circle w0.254: c0.762,-4.826 r2.54
  circle w0.254: c67.056,-4.826 r2.54

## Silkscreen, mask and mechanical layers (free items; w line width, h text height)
Top Overlay:
  text "VDD" at 23.114,55 h0.84 r90
  text "P40" at 26.035,55 h0.84 r90
  text "P41" at 28.575,55 h0.84 r90
  text "P42" at 31.115,55 h0.84 r90
  text "P43" at 33.655,55 h0.84 r90
  text "P00" at 36.195,55 h0.84 r90
  text "P01" at 38.481,55 h0.84 r90
  text "P46" at 41.275,55 h0.84 r90
  text "RST" at 43.434,55 h0.84 r90
  text "GND" at 45.974,55 h0.84 r90
  text "VDD" at 20.193,54.873 h0.84 r90
  text "VREF+" at 13.208,52.832 h1.27
  text "VDD" at 49.657,52.705 h0.84
  text "ISP" at 59.944,51.816 h1.14
  text "VDD" at 4.953,50.292 h0.84 r90
  text "P60" at 49.657,50.165 h0.84
  text "GND" at 20.193,49.911 h0.84 r90
  text "VDD" at 58.928,49.149 h0.84 r90
  text "P70" at 4.953,47.752 h0.84 r90
  text "P57" at 19.431,47.752 h0.84
  text "P61" at 49.657,47.625 h0.84
  text "P31" at 58.928,46.736 h0.84 r90
  text "P56" at 19.431,45.339 h0.84
  text "P71" at 4.953,45.212 h0.84 r90
  text "P62" at 49.657,45.085 h0.84
  text "GND" at 58.928,43.942 h0.84 r90
  text "P55" at 19.431,42.799 h0.84
  text "P63" at 49.657,42.545 h0.84
  text "P72" at 4.953,42.418 h0.84 r90
  text "P54" at 19.431,40.259 h0.84
  text "P64" at 49.657,40.005 h0.84
  text "GND" at 4.953,39.37 h0.84 r90
  text "P65" at 49.657,37.973 h0.84
  text "P53" at 19.431,37.719 h0.84
  text "RST" at 8.89,37.338 h0.84
  text "Power Off" at 58.42,36.83 h1.02 r90
  text "Power On" at 69.85,36.83 h1.02 r90
  text "P66" at 49.657,35.814 h0.84
  text "P52" at 19.431,35.179 h0.84
  text "GND" at 8.89,35.052 h0.84
  text "VDD" at 61.849,34.925 h0.84 r90
  text "VDD5" at 60.325,34.798 h0.84 r90
  text "VDD3" at 63.373,34.798 h0.84 r90
  text "P51" at 19.431,32.639 h0.84
  text "P67" at 49.657,32.639 h0.84
  text "SDA" at 8.89,32.258 h0.84
  text "P50" at 19.431,30.099 h0.84
  text "GND" at 49.657,29.845 h0.84
  text "VDD" at 8.89,29.718 h0.84
  text "ICE/ICP" at 12.446,27.686 h1.14 r90
  text "VDD" at 19.431,27.559 h0.84
  text "SCL" at 8.89,27.178 h0.84
  text "P30" at 8.89,24.892 h0.84
  text "VDD" at 69.088,23.114 h1.27 r90
  text "P02" at 8.382,21.9 h0.97 r90
  text "P03" at 10.693,21.9 h0.97 r90
  text "P04" at 13.233,21.9 h0.97 r90
  text "P05" at 16.256,21.9 h0.97 r90
  text "P06" at 18.339,21.9 h0.97 r90
  text "P07" at 20.828,21.9 h0.97 r90
  text "P46" at 25.908,21.9 h0.97 r90
  text "P27" at 30.734,21.9 h0.89 r90
  text "P26" at 33.528,21.9 h0.89 r90
  text "P25" at 36.068,21.9 h0.89 r90
  text "P24" at 38.608,21.9 h0.89 r90
  text "P23" at 41.148,21.9 h0.89 r90
  text "P22" at 44.704,21.9 h0.89 r90
  text "P21" at 46.99,21.9 h0.89 r90
  text "P20" at 48.768,21.9 h0.89 r90
  text "VDD" at -1.778,21.844 h1.02
  text "P44" at 1.27,21.844 h1.02
  text "P45" at 4.318,21.844 h1.02
  text "GND" at 63.246,18.288 h0.84
  text "D+" at 63.119,16.002 h0.84
  text "D-" at 63.119,14.859 h0.84
  text "VDD" at 63.246,13.081 h0.84
  text "P31" at 29.21,12.192 h0.89
  text "MA82G5C64" at 11.684,11.684 h1.14
  text "LQFP64_V10" at 11.684,9.652 h1.14
  text "P30" at 28.956,9.652 h0.89
  text "Ev Board" at 11.684,7.628 h1.14
  text "P43" at 28.956,7.112 h0.89
  text "GND" at 69.215,6.985 h1.27 r90
  text "TH167A" at 11.684,5.842 h1.14
  text "USB_Ok" at 58.166,3.048 h0.97
  text "P10" at -2.032,-2.54 h1.02
  text "P11" at 2.032,-2.54 h1.02
  text "RST" at 18.669,-2.54 h1.02
  text "P30" at 21.844,-2.54 h1.02
  text "P32" at 26.67,-2.54 h1.02
  text "P33" at 29.718,-2.54 h1.02
  text "P34" at 32.766,-2.54 h1.02
  text "USB_Busy" at 57.15,-3.556 h0.97
  text "P31" at 25.908,-3.683 h1.02 r90
  text "P35" at 36.703,-3.937 h1.02 r90
  text "P36" at 38.659,-3.937 h1.02 r90
  text "P37" at 41.021,-3.937 h0.89 r90
  text "P60" at 43.688,-3.937 h0.89 r90
  text "P61" at 46.228,-3.937 h0.9 r90
  text "GND" at 49.022,-3.937 h0.9 r90
  text "P12" at 5.588,-4.1 h1.02 r90
  text "P13" at 8.128,-4.1 h1.02 r90
  text "P14" at 10.668,-4.1 h1.02 r90
  text "P15" at 13.054,-4.1 h1.02 r90
  text "P16" at 15.594,-4.1 h1.02 r90
  text "P17" at 18.134,-4.1 h1.02 r90
  text "Reset" at 28.321,-7.62 h1.02
Mechanical 1:
  the board outline again, w0.33

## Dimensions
-2.286,58.126 to -2.286,-7.874 on Top Overlay
-2.286,-7.874 to 70.114,-7.874 on Top Overlay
